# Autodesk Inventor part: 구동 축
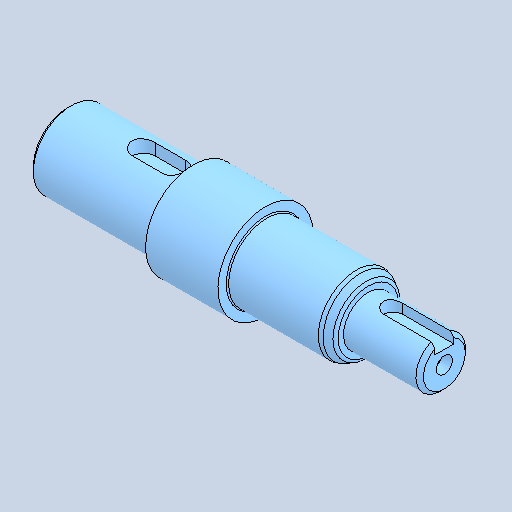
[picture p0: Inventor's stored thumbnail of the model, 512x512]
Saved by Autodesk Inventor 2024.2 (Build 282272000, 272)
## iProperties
Created: 2025-09
Part Number: 구동 축
Material: 강철, 탄소
Document SubType Name: Modeling
Designer: home
Density: 7.85 g/cm^3
Appearance: 기본값
Author: jhkim
Sending System: Autodesk Inventor 2026
Preprocessor: ST-DEVELOPER v20.1
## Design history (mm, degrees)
feature "솔리드1"
node "솔리드2"
